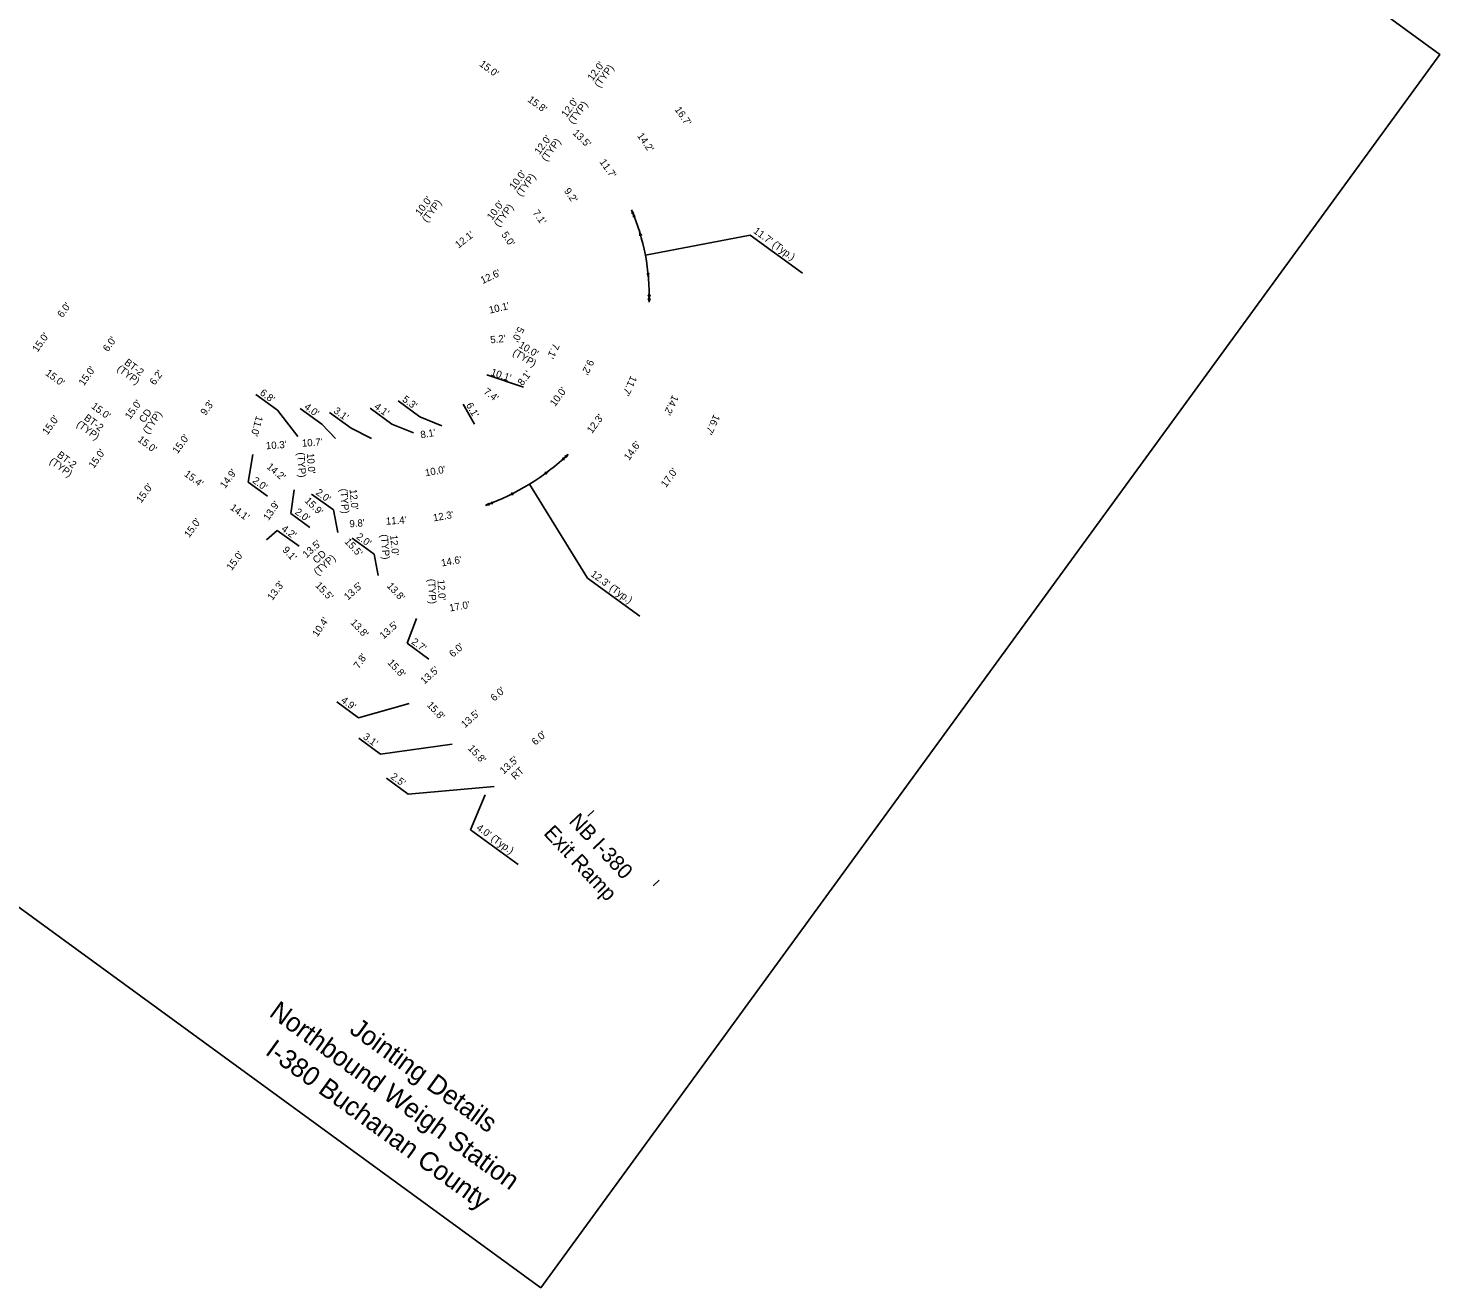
# Model space of a CAD drawing. Extents: x 15567221 to 15568484, y 8782768 to 8783889.
# Drawn here: x 15568114 to 15568484, y 8782919.5 to 8783249.6 of the extents above; entities that cross this region are included whole.
import ezdxf

# ---------------------------------------------------------------- set-up
doc = ezdxf.new("R2010")
doc.units = 0
for name, color, linetype in [('Drainage', 7, 'Continuous'), ('EXT_C', 7, 'Continuous'), ('EXT_EP', 7, 'Continuous'), ('EXT_GU', 7, 'Continuous'), ('NamedBoundary', 7, 'Continuous'), ('TextAlignmentSml', 7, 'Continuous')]:
    doc.layers.add(name, color=color, linetype=linetype)

msp = doc.modelspace()

# ---------------------------------------------------------------- linework, layer by layer
at = {"layer": 'Drainage'}
for p, q in [((15568275.74, 8783190.19), (15568303.25, 8783195.42)), ((15568316.9, 8783185.46), (15568303.25, 8783195.42)), ((15568179.33, 8783149.52), (15568173.61, 8783153.69)), ((15568190.94, 8783145.84), (15568185.22, 8783150.01)), ((15568209.29, 8783145.92), (15568203.57, 8783150.09)), ((15568216.63, 8783147.8), (15568210.91, 8783151.97)), ((15568184.62, 8783142.69), (15568179.33, 8783149.52)), ((15568198.65, 8783144.79), (15568192.93, 8783148.96)), ((15568222.41, 8783145.46), (15568216.63, 8783147.8)), ((15568194.53, 8783142.16), (15568190.94, 8783145.84)), ((15568203.97, 8783142.16), (15568198.65, 8783144.79)), ((15568214.93, 8783143.63), (15568209.29, 8783145.92)), ((15568172.82, 8783137.91), (15568171.66, 8783130.69)), ((15568176.68, 8783127.03), (15568171.66, 8783130.69)), ((15568183.72, 8783128.69), (15568182.8, 8783122.47)), ((15568193.98, 8783123.4), (15568188.26, 8783127.57)), ((15568245.38, 8783130.17), (15568260.6, 8783105.49)), ((15568187.83, 8783118.81), (15568182.8, 8783122.47)), ((15568195.14, 8783117.53), (15568193.98, 8783123.4)), ((15568176.47, 8783115.59), (15568179.24, 8783118.05)), ((15568184.96, 8783113.88), (15568179.24, 8783118.05)), ((15568204.62, 8783111.82), (15568198.9, 8783115.99)), ((15568205.73, 8783106.25), (15568204.62, 8783111.82)), ((15568274.26, 8783095.53), (15568260.6, 8783105.49)), ((15568215.77, 8783094.97), (15568213.31, 8783088.45)), ((15568219.03, 8783084.28), (15568213.31, 8783088.45)), ((15568200.59, 8783068.93), (15568194.87, 8783073.1)), ((15568213.82, 8783072.68), (15568200.59, 8783068.93)), ((15568206.35, 8783059.39), (15568200.63, 8783063.56)), ((15568225.11, 8783061.98), (15568206.35, 8783059.39)), ((15568213.6, 8783048.94), (15568207.89, 8783053.11)), ((15568236.1, 8783050.95), (15568213.6, 8783048.94)), ((15568233.72, 8783048.71), (15568229.92, 8783039.53)), ((15568242.37, 8783030.45), (15568229.92, 8783039.53))]:
    msp.add_line(p, q, dxfattribs=at)
for centre, radius, start, end in [((15568219.35, 8783179.46), 57.4, 358.3626, 23.1754), ((15568212.47, 8783183.55), 62.71, 289.935, 313.3762)]:
    msp.add_arc(centre, radius, start, end, dxfattribs=at)
at = {"layer": 'EXT_C'}
for p, q in [((15568243.79, 8783155.57), (15568234.18, 8783158.79)), ((15568230.97, 8783145.85), (15568227.96, 8783151.12))]:
    msp.add_line(p, q, dxfattribs=at)
at = {"layer": 'EXT_GU'}
for p, q in [((15568272.12, 8783202.05), (15568272.31, 8783201.61)), ((15568272.12, 8783202.05), (15568272.49, 8783201.17)), ((15568272.49, 8783201.17), (15568272.67, 8783200.72)), ((15568272.49, 8783201.17), (15568272.85, 8783200.27)), ((15568274.24, 8783196.24), (15568274.38, 8783195.78)), ((15568274.24, 8783196.24), (15568274.52, 8783195.32)), ((15568276.53, 8783184.53), (15568276.43, 8783185.48)), ((15568276.53, 8783184.53), (15568276.48, 8783185.01)), ((15568276.75, 8783178.78), (15568276.75, 8783179.74)), ((15568276.75, 8783178.78), (15568276.75, 8783179.27)), ((15568276.73, 8783177.82), (15568276.75, 8783178.78)), ((15568276.73, 8783177.82), (15568276.74, 8783178.31)), ((15568254.84, 8783137.32), (15568254.12, 8783136.67)), ((15568254.84, 8783137.32), (15568254.48, 8783136.99)), ((15568255.54, 8783137.97), (15568254.84, 8783137.32)), ((15568255.54, 8783137.97), (15568255.19, 8783137.64)), ((15568250.37, 8783133.59), (15568249.6, 8783133.01)), ((15568250.37, 8783133.59), (15568249.98, 8783133.3)), ((15568240.1, 8783127.26), (15568240.96, 8783127.69)), ((15568240.1, 8783127.26), (15568240.53, 8783127.47)), ((15568233.85, 8783124.6), (15568234.76, 8783124.94)), ((15568233.85, 8783124.6), (15568234.31, 8783124.77)), ((15568234.76, 8783124.94), (15568235.65, 8783125.28)), ((15568234.76, 8783124.94), (15568235.21, 8783125.11))]:
    msp.add_line(p, q, dxfattribs=at)
for centre, radius, start, end in [((15568270.16, 8783201.23), 2.12, 354.62, 22.6925), ((15568274.08, 8783202.87), 2.12, 202.6925, 230.765), ((15568272.81, 8783200.41), 0.821, 94.9592, 130.4259), ((15568270.52, 8783200.38), 2.12, 353.6608, 21.7333), ((15568274.46, 8783201.95), 2.12, 201.7333, 229.8058), ((15568273.15, 8783199.51), 0.821, 93.9999, 129.4666), ((15568272.21, 8783195.64), 2.12, 348.4395, 16.512), ((15568276.28, 8783196.84), 2.12, 196.512, 224.5844), ((15568274.75, 8783194.53), 0.821, 88.7786, 124.2453), ((15568276.35, 8783186.3), 0.821, 257.807, 293.2737), ((15568274.41, 8783184.32), 2.12, 5.5403, 33.6128), ((15568278.64, 8783184.73), 2.12, 157.4678, 185.5403), ((15568276.75, 8783180.57), 0.821, 252.0665, 287.5332), ((15568274.62, 8783178.79), 2.12, 359.7998, 27.8723), ((15568278.87, 8783178.78), 2.12, 151.7273, 179.7998), ((15568276.76, 8783179.6), 0.821, 251.1072, 286.5739), ((15568274.6, 8783177.87), 2.12, 358.8406, 26.9131), ((15568278.85, 8783177.78), 2.12, 150.7681, 178.8406), ((15568253.41, 8783138.9), 2.12, 283.9845, 312.057), ((15568253.51, 8783136.12), 0.821, 24.3237, 59.7904), ((15568256.26, 8783135.74), 2.12, 132.057, 160.1295), ((15568254.09, 8783139.53), 2.12, 284.8626, 312.9351), ((15568254.24, 8783136.76), 0.821, 25.2018, 60.6685), ((15568256.99, 8783136.42), 2.12, 132.9351, 161.0076), ((15568249.1, 8783135.29), 2.12, 278.6644, 306.7369), ((15568248.94, 8783132.52), 0.821, 19.0035, 54.4702), ((15568251.64, 8783131.89), 2.12, 126.7369, 154.8093), ((15568239.15, 8783129.16), 2.12, 296.5733, 324.6458), ((15568241.05, 8783125.35), 2.12, 88.5008, 116.5733), ((15568241.69, 8783128.05), 0.821, 188.8399, 224.3066), ((15568233.11, 8783126.59), 2.12, 290.3738, 318.4462), ((15568234.59, 8783122.61), 2.12, 82.3013, 110.3738), ((15568235.52, 8783125.22), 0.821, 182.6404, 218.1071), ((15568233.99, 8783126.92), 2.12, 291.2518, 319.3243), ((15568235.53, 8783122.96), 2.12, 83.1793, 111.2518), ((15568236.42, 8783125.58), 0.821, 183.5185, 218.9852)]:
    msp.add_arc(centre, radius, start, end, dxfattribs=at)
at = {"layer": 'NamedBoundary'}
msp.add_lwpolyline([(15568248.32, 8782919.55), (15568483.96, 8783242.77), (15567982.56, 8783608.32), (15567746.92, 8783285.1)], close=True, dxfattribs=at)
at = {"layer": 'TextAlignmentSml'}
for p, q in [((15568262.27, 8783044.61), (15568260.68, 8783043.11)), ((15568279.39, 8783026.39), (15568277.8, 8783024.89))]:
    msp.add_line(p, q, dxfattribs=at)

# ---------------------------------------------------------------- texts
at = {"layer": 'Drainage'}
for s, height, rotation, p in [("15.0'", 1.89, 323.584, (15568232.08, 8783239.92)), ("12.0'", 1.89, 53.4236, (15568261.9, 8783235.71)), ('(TYP)', 1.89, 53.4236, (15568263.68, 8783233.94)), ("15.8'", 1.89, 323.5838, (15568244.73, 8783230.59)), ("12.0'", 1.89, 53.4236, (15568255.05, 8783226.14)), ('(TYP)', 1.89, 53.4236, (15568256.83, 8783224.37)), ("16.7'", 1.89, 304.8026, (15568283.34, 8783228.33)), ("12.0'", 1.89, 53.4236, (15568247.99, 8783216.4)), ('(TYP)', 1.89, 53.4236, (15568249.77, 8783214.62)), ("13.5'", 1.89, 315.2515, (15568256.55, 8783222.05)), ("14.2'", 1.89, 304.8026, (15568273.5, 8783221.46)), ("10.0'", 1.89, 53.4236, (15568241.42, 8783207.19)), ("11.7'", 1.89, 304.8026, (15568263.65, 8783214.6)), ('(TYP)', 1.89, 53.4236, (15568243.2, 8783205.41)), ("10.0'", 1.89, 53.4236, (15568216.74, 8783200.36)), ("9.2'", 1.89, 304.8026, (15568254.33, 8783206.99)), ('(TYP)', 1.89, 53.4236, (15568218.52, 8783198.59)), ("10.0'", 1.89, 53.4236, (15568235.57, 8783199.2)), ('(TYP)', 1.89, 53.4236, (15568237.36, 8783197.42)), ("7.1'", 1.89, 304.8026, (15568246.13, 8783201.27)), ("12.1'", 1.89, 38.0921, (15568226.78, 8783191.87)), ("5.0'", 1.89, 304.8026, (15568237.92, 8783195.55)), ("11.7' (Typ.)", 1.8898, 323.9055, (15568303.89, 8783196.15)), ("12.6'", 1.89, 24.6852, (15568233.07, 8783182.6)), ("6.0'", 1.89, 53.9364, (15568122.94, 8783173.66)), ("10.1'", 1.89, 13.1299, (15568234.98, 8783174.85)), ("15.0'", 1.89, 54.3971, (15568116.42, 8783164.61)), ("6.0'", 1.89, 53.9364, (15568134.89, 8783164.73)), ("5.2'", 1.89, 5.3968, (15568235.18, 8783167.06)), ("5.0'", 1.89, 244.8907, (15568242.41, 8783171.58)), ('(TYP)', 1.89, 329.2649, (15568240.78, 8783164.15)), ("10.0'", 1.89, 329.2649, (15568242.37, 8783166.1)), ("7.1'", 1.89, 244.8907, (15568251.64, 8783167.23)), ("15.0'", 1.89, 54.3971, (15568128.57, 8783155.8)), ('(TYP)', 1.89, 323.3841, (15568137.06, 8783160.05)), ('BT-2', 1.89, 323.3841, (15568139.02, 8783161.69)), ("9.2'", 1.89, 244.8907, (15568260.7, 8783163)), ("15.0'", 1.89, 323.3841, (15568118.32, 8783158.91)), ("6.2'", 1.89, 53.9364, (15568147.14, 8783155.96)), ("10.1'", 1.89, 341.4744, (15568235.08, 8783158.75)), ("8.1'", 1.89, 51.7771, (15568243.53, 8783155.82)), ("11.7'", 1.89, 244.8922, (15568271.96, 8783158.74)), ("6.8'", 1.89, 323.7364, (15568174.54, 8783153.74)), ("5.3'", 1.89, 323.7364, (15568211.85, 8783152.02)), ("7.4'", 1.89, 323.0387, (15568233.19, 8783154.06)), ("10.0'", 1.89, 53.8925, (15568252.08, 8783150.37)), ("14.2'", 1.89, 244.8907, (15568282.84, 8783153.67)), ("15.0'", 1.89, 323.3841, (15568130.36, 8783150.24)), ("15.0'", 1.89, 54.3971, (15568140.71, 8783147)), ('CD', 1.89, 55.561, (15568144.41, 8783146.07)), ("9.3'", 1.89, 53.9364, (15568160.46, 8783148.02)), ("4.0'", 1.89, 323.7364, (15568186.15, 8783150.06)), ("3.1'", 1.89, 323.7364, (15568193.86, 8783149.01)), ("4.1'", 1.89, 323.7364, (15568204.5, 8783150.13)), ("6.1'", 1.89, 299.7856, (15568228.67, 8783150.89)), ("15.0'", 1.89, 54.3971, (15568119.03, 8783142.92)), ('(TYP)', 1.89, 323.3841, (15568126.48, 8783145.53)), ('BT-2', 1.89, 323.3841, (15568128.44, 8783147.18)), ('(TYP)', 1.89, 55.561, (15568145.41, 8783143.12)), ("11.0'", 1.89, 254.0476, (15568173.77, 8783148.2)), ("12.3'", 1.89, 53.8925, (15568261.77, 8783143.29)), ("16.7'", 1.89, 244.8907, (15568293.71, 8783148.59)), ("15.0'", 1.89, 323.3841, (15568142.5, 8783141.5)), ("15.0'", 1.89, 53.584, (15568153.13, 8783137.99)), ("8.1'", 1.89, 9.7055, (15568216.95, 8783142.16)), ('BT-2', 1.89, 323.3841, (15568121.36, 8783137.46)), ("15.0'", 1.89, 54.3971, (15568131.17, 8783134.12)), ("10.3'", 1.89, 4.0476, (15568176.35, 8783139.28)), ("10.7'", 1.89, 4.0476, (15568185.78, 8783139.95)), ("14.6'", 1.89, 53.8925, (15568271.47, 8783136.22)), ('(TYP)', 1.89, 323.3841, (15568119.39, 8783135.82)), ("14.2'", 1.89, 319.6136, (15568176.33, 8783134.47)), ('(TYP)', 1.89, 274.0476, (15568184.49, 8783138.43)), ("10.0'", 1.89, 274.0476, (15568187, 8783138.24)), ("10.0'", 1.89, 10.174, (15568218.16, 8783132.2)), ("15.4'", 1.89, 323.3841, (15568154.69, 8783132.47)), ("14.9'", 1.89, 53.584, (15568165.58, 8783128.87)), ("2.0'", 1.89, 323.7364, (15568172.59, 8783130.74)), ("17.0'", 1.89, 53.8925, (15568281.16, 8783129.15)), ("15.0'", 1.89, 53.584, (15568143.59, 8783125.11)), ("2.0'", 1.89, 323.7364, (15568189.2, 8783127.62)), ('(TYP)', 1.89, 274.8368, (15568195.71, 8783128.93)), ("12.0'", 1.89, 274.8368, (15568198.22, 8783128.78)), ("14.1'", 1.89, 323.3841, (15568166.74, 8783123.68)), ("13.9'", 1.89, 55.561, (15568176.96, 8783120.48)), ("2.0'", 1.89, 323.7364, (15568183.73, 8783122.52)), ("15.9'", 1.89, 315.8048, (15568186.31, 8783125.63)), ("15.0'", 1.89, 53.584, (15568156.17, 8783116)), ("9.8'", 1.89, 4.0476, (15568198.24, 8783118.83)), ("11.4'", 1.89, 4.0476, (15568207.78, 8783119.51)), ("12.3'", 1.89, 10.174, (15568220.28, 8783120.38)), ("4.2'", 1.89, 323.7364, (15568180.17, 8783118.1)), ("2.0'", 1.89, 323.7364, (15568199.83, 8783116.04)), ('(TYP)', 1.89, 274.8368, (15568206.35, 8783116.94)), ("12.0'", 1.89, 274.8368, (15568208.86, 8783116.78)), ("15.0'", 1.89, 53.584, (15568167.31, 8783107.39)), ("9.1'", 1.89, 312.9466, (15568180.48, 8783112.8)), ("13.5'", 1.89, 42.0448, (15568186.94, 8783110.7)), ('CD', 1.89, 42.0448, (15568189.56, 8783109.21)), ("15.5'", 1.89, 312.9466, (15568196.76, 8783114.98)), ('(TYP)', 1.89, 42.0448, (15568189.84, 8783106.11)), ("14.6'", 1.89, 10.174, (15568222.4, 8783108.57)), ("12.3' (Typ.)", 1.8898, 323.9055, (15568261.24, 8783106.21)), ("13.3'", 1.89, 53.584, (15568177.99, 8783099.54)), ("15.5'", 1.89, 312.9466, (15568189.1, 8783103.5)), ("13.5'", 1.89, 42.0448, (15568197.77, 8783099.63)), ("13.8'", 1.89, 312.9466, (15568207.87, 8783103.37)), ('(TYP)', 1.89, 273.2026, (15568218.74, 8783105.3)), ("12.0'", 1.89, 273.2026, (15568221.25, 8783105.07)), ("17.0'", 1.89, 10.174, (15568224.52, 8783096.76)), ("10.4'", 1.89, 55.561, (15568189.79, 8783089.99)), ("13.8'", 1.89, 312.9466, (15568198.32, 8783093.75)), ("13.5'", 1.89, 42.0448, (15568207.12, 8783089.43)), ("2.7'", 1.89, 323.7364, (15568214.25, 8783088.5)), ("6.0'", 1.89, 41.4817, (15568225.33, 8783084.65)), ("7.8'", 1.89, 55.561, (15568200.66, 8783081.64)), ("15.8'", 1.89, 312.9466, (15568208.05, 8783083.25)), ("13.5'", 1.89, 42.0448, (15568217.82, 8783077.59)), ("6.0'", 1.89, 41.4817, (15568236.16, 8783073.14)), ("4.9'", 1.89, 323.7364, (15568195.8, 8783073.15)), ("15.8'", 1.89, 312.9466, (15568218.34, 8783072.15)), ("13.5'", 1.89, 42.0448, (15568228.47, 8783066.17)), ("3.1'", 1.89, 323.7364, (15568201.57, 8783063.61)), ("6.0'", 1.89, 41.4817, (15568246.95, 8783061.6)), ("15.8'", 1.89, 312.9466, (15568229.13, 8783060.79)), ("13.5'", 1.89, 42.0448, (15568238.61, 8783054.04)), ("2.5'", 1.89, 323.7364, (15568208.82, 8783053.16)), ('RT', 1.89, 42.0448, (15568241.6, 8783052.56)), ("4.0' (Typ.)", 1.8898, 323.9055, (15568231.29, 8783039.73))]:
    msp.add_text(s, height=height, rotation=rotation, dxfattribs=at).set_placement(p)
at = {"layer": 'EXT_EP'}
for s, height, rotation, p in [('NB I-380', 3.99, 313.2123, (15568255.49, 8783041.62)), ('Exit Ramp', 3.99, 313.2123, (15568248.86, 8783038.49)), ('Northbound Weigh Station', 5, 324.0689, (15568176.87, 8782990.96)), ('Jointing Details', 5, 324.0689, (15568197.87, 8782986.55)), ('I-380 Buchanan County', 5, 324.0689, (15568175.84, 8782980.9))]:
    msp.add_text(s, height=height, rotation=rotation, dxfattribs=at).set_placement(p)

doc.saveas('drawing.dxf')
